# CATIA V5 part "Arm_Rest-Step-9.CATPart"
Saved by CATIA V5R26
Part number: Arm_Rest
Bounding box of the stored display mesh (mm): x 746.599 to 1432.298, y -782.976 to -630.25, z 345.981 to 524.952
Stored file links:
  D:\LinkedIn Learning\NURBS\CATIA\Class Parts\Arm_Rest-Step-10.CATPart
  D:\LinkedIn Learning\NURBS\Arm_Rest.CATPart
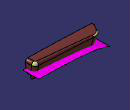
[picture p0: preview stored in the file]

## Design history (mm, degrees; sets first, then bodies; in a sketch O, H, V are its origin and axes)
AxisSystem1: origin (0, 0, 0), X (1, 0, 0), Y (0, 1, 0), Z (0, 0, 1)
StDynAnalysisRootNodeFeature1 "CATStDynAnalysisRootNodeName"
Set1 "REF DATA"
  CLDGeom1 "TOP"
  CLDGeom2 "FRONT"
  CLDGeom3 "AFT_BLEND"
  CLDGeom4 "END_AFT"
  CLDGeom5 "FORWARD_BLEND"
  CLDGeom6 "BOTTOM"
  CLDGeom7 "END_FORWARD"
  CLDGeom8 "UPPER_BLENDS"
  CLDGeom9 "LOWER_BLENDS"
  DatumSurface1 "DOOR_TRIM_SURFACE"
Set2 "FORM"
  Set3 "SLABS"
    DatumSurface2 to DatumSurface6
  Set4 "CURVES"
    St3DCurveFeature1 "CATSt3DCurveFeatureName": Order 6, CreationType 1, ClosureMode false, ConstructionPoints ({point type Coord, X 863.1168, Y 0, Z 551.1449}; {point type Coord, X 868.9503, Y 0, Z 330.43}), SymmetryMode false
    St3DCurveFeature2 "CATSt3DCurveFeatureName": Order 6, CreationType 1, ClosureMode false, ConstructionPoints ({point type Coord, X 1369.3867, Y 0, Z 551.9965}; {point type Coord, X 1358.4038, Y 0, Z 335.6826}), SymmetryMode false
    Intersect1: ToIntersect1 DatumSurface4, ToIntersect2 DatumSurface5
    Intersect2: ToIntersect1 DatumSurface6, ToIntersect2 DatumSurface4
    CurvePar1: Offset Intersect2, Support DatumSurface6, Offset2 0, Offset1 30
    CurvePar2: Offset Intersect1, Support DatumSurface5, Offset2 50, Offset1 20
    Project1: ToProject St3DCurveFeature1, Support DatumSurface4, Direction edge [YZ plane of AxisSystem1 | XY plane of AxisSystem1]
    Project2: ToProject St3DCurveFeature2, Support DatumSurface4, Direction edge [YZ plane of AxisSystem1 | XY plane of AxisSystem1]
    Project3: ToProject St3DCurveFeature2, Support StTopoTypeFeature3, Direction edge [YZ plane of AxisSystem1 | XY plane of AxisSystem1]
    Project4: ToProject St3DCurveFeature1, Support StTopoTypeFeature3, Direction edge [YZ plane of AxisSystem1 | XY plane of AxisSystem1]
    Intersect3: ToIntersect1 edge of StTopoTypeFeature1, ToIntersect2 CurvePar2
    Intersect4: ToIntersect1 edge of StTopoTypeFeature2, ToIntersect2 CurvePar1
    Project5: ToProject Intersect4, Support edge of StTopoTypeFeature2
    Project6: ToProject Intersect3, Support edge of StTopoTypeFeature1
    Line1: type PtPt, FirstPoint Intersect3, SecondPoint Project6, Support StTopoTypeFeature1
    Line2: type PtPt, FirstPoint Intersect4, SecondPoint Project5, Support StTopoTypeFeature2
    Curve1: Elements (Intersect4; vertex of Project3), Support Blend2
    Curve2: Elements (Project5; vertex of Project3), Support DatumSurface2
    Curve3: Elements (vertex of Project4; Intersect3), Support Blend1
    Curve4: Elements (vertex of Project4; Project6), Support DatumSurface2
  Set5 "BLENDS"
    Blend1: StartLimit {blendlimit Curve Project1, Support DatumSurface4, TensionValues 1.1}, EndLimit {blendlimit Curve CurvePar2, Support DatumSurface5, TensionValues 1}
    Blend2: StartLimit {blendlimit Curve CurvePar1, Support DatumSurface6, TensionValues 0.9}, EndLimit {blendlimit Curve Project2, Support DatumSurface4, TensionValues 0.8}
    StTopoTypeFeature1 "CATStTopoTypeFeatureName": Children 15
    StTopoTypeFeature2 "CATStTopoTypeFeatureName": Children 35
    StTopoTypeFeature3 "CATStTopoTypeFeatureName": nls://CATStFeaturesStartUpsNLS/TopoVarRadiCke 35, nls://CATStFeaturesStartUpsNLS/TopoVarRadiCke 15
    Loft1: Sections (Line2; Project3), StartSectionTangent StTopoTypeFeature2, EndSectionTangent StTopoTypeFeature3, Guides ({loftguide GuideCurve Curve1, GuideTangent Blend2}; {loftguide GuideCurve Curve2, GuideTangent DatumSurface2})
    Loft2: Sections (Project4; Line1), StartSectionTangent StTopoTypeFeature3, EndSectionTangent StTopoTypeFeature1, Guides ({loftguide GuideCurve Curve3, GuideTangent Blend1}; {loftguide GuideCurve Curve4, GuideTangent DatumSurface2})
  Set6 "SPLITS"
    Split1: ToCut DatumSurface4, Cutting (Project1; edge of StTopoTypeFeature3; Project2)
    Split2: ToCut Blend2, Cutting Curve1
    Split3: ToCut DatumSurface6, Cutting (CurvePar1; edge of StTopoTypeFeature2)
    Split4: ToCut Blend1, Cutting Curve3
    Split5: ToCut DatumSurface5, Cutting (CurvePar2; edge of StTopoTypeFeature1)
    Split6: ToCut StTopoTypeFeature1, Cutting Line1
    Split7: ToCut StTopoTypeFeature3, Cutting (Project4; Project3)
    Split8: ToCut StTopoTypeFeature2, Cutting Line2
    Split9: ToCut DatumSurface2, Cutting (edge of StTopoTypeFeature3; edge of StTopoTypeFeature2; Curve2; edge of StTopoTypeFeature1; Curve4)
Body1 (main body)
